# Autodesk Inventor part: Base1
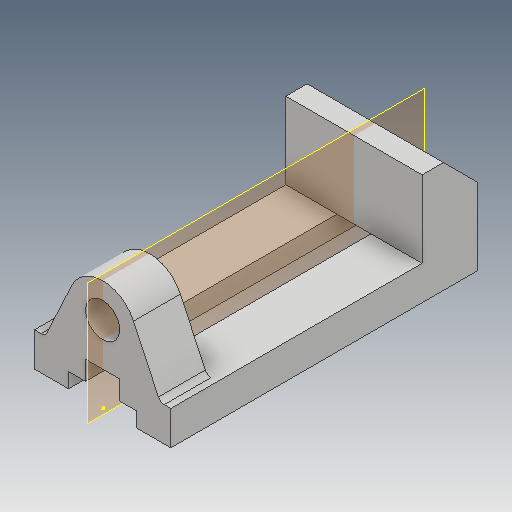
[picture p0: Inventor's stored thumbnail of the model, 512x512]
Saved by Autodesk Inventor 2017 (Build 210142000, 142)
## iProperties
Created: 2016-03
Part Number: Base1
Material: Generic
Document SubType Name: Modeling
Designer: Sandeep
Density: 1 g/cm^3
Appearance: Default
Author: Sandeep
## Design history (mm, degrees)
sketch "Sketch1"
  geometry: L1 (0, 0)-(0, 16); L2 (0, 16)-(118, 16); L3 (118, 16)-(118, 52); L4 (118, 52)-(144, 52); L5 (144, 52)-(144, 0); L6 (144, 0)-(0, 0)
  constraints: 12 end point, 3 perpendicular, 1 vertical
  dimensions: "d1" = 144 distance of L5.end L1.start; "d2" = 26 distance of L3.end L4.end; "d3" = 16 distance between parallel lines of L6 L2; "d4" = 36 distance between parallel lines of L2 L4
extrude "Extrusion1" new body sketch "Sketch1" stored distance "d5" = 64; taper "d6" = 0 deg
chamfer "Chamfer1" distance "d7" = 16; stored, may be unused: second distance "d8" = 16, angle "d9" = 45 deg
sketch "Sketch4"
  geometry: 1 further point
sketch "Sketch5"
  geometry: L1 (-16, 5.02)-(-42.762, 17.499); L2 (-42.762, 46.501)-(-16, 58.98); L3 (-52, 64)-(-52, 0) reference; L4 (-16, 32)-(-54.774, 32); L5 (-52, 64)-(-16, 64) reference; L6 (-16, 64)-(-16, 0) reference; L7 (-16, 5.02)-(-16, 58.98); L8 (0, 64)-(0, 0) reference; A1 r 16 centre (-36, 32) between (-42.762, 46.501) and (-42.762, 17.499); 1 further point
  constraints: 8 end point, 3 point on line, 3 tangent, 2 point on circle, 1 centre point, 1 collinear, 1 horizontal, 1 other
  dimensions: "d21" = 50 deg angle of L2 L1; "d22" = 36 distance from line of L8 A1.centre
extrude "Extrusion2" join sketch "Sketch5" distance "d23" = 22; taper "d24" = 0 deg
fillet "Fillet1" dims "d25" = 3
sketch "Sketch6"
  geometry: L1 (-36, 64)-(-36, 0) reference; C1 r 8 at (-36, 32); A1 r 16 centre (-36, 32) between (-42.762, 46.501) and (-42.762, 17.499) reference; 1 further point
  constraints: 1 centre point, 1 concentric, 1 midpoint
  dimensions: "d26" = 16 diameter of C1
extrude "Extrusion3" cut sketch "Sketch6" distance "d27" = 22; taper "d28" = 0 deg
sketch "Sketch7"
  geometry: L1 (0, 0)-(0, 64) reference; L2 (0, 16)-(-7, 16); L3 (-7, 16)-(-7, 24); L4 (-7, 24)-(-16, 24); L5 (-16, 3.109)-(-16, 60.891) reference; L6 (-16, 24)-(-16, 40); L7 (-7, 40)-(-7, 48); L8 (-7, 48)-(0, 48); L9 (0, 48)-(0, 16); L10 (-7, 40)-(-16, 40); L11 (-44, 32)-(-36, 32); 1 further point
  constraints: 18 end point, 6 point on line, 4 perpendicular, 2 horizontal, 1 collinear, 1 horizontal alignment, 4 other
  dimensions: "d29" = 32 distance between parallel lines of L2 L8; "d30" = 7 distance of L7.end L8.end; "d45" = 16 distance between parallel lines of L10 L4
extrude "Extrusion4" cut sketch "Sketch7" distance "d31" = 167.75; taper "d32" = 0 deg
sketch "Sketch8"
  geometry: L1 (144, 0)-(144, -16) reference; L2 (0, 0)-(144, 0) reference; L3 (0, -16)-(0, 0) reference; 3 further points
  dimensions: "d33" = 70 distance of point (108, -10) point (38, -10); "d35" = 10 distance from line of L2 point (108, -10); "d36" = 10 distance from line of L2 point (38, -10); "d46" = 38 distance from line of L3 point (38, -10)
hole "Hole1" sketch "Sketch8" at (38, -10), (108, -10) diameter "d37" = 4.917; stored, may be unused: countersink angle "d41" = 90 deg, drill point angle "d43" = 118 deg; dims "d38" = 12, "d39" = 4, "d40" = 2, "d42" = 10
workplane "Work Plane1"
mirror "Mirror1"
body "Solid1"
other parameters: "d10" = 16, "d13" = 7, "d14" = 16, "d44" = -32
